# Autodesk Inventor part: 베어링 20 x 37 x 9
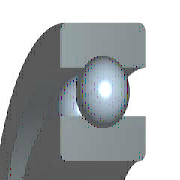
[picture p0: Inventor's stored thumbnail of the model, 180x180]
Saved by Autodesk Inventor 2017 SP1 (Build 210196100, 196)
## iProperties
IsCustomPart: 1
Created: 2012-02
Part Number: 베어링 20 x 37 x 9
Material: 강철, 연강
Description: 깊은 그루브 볼 베어링
Document SubType Name: Modeling
Standard: KS B 2023
Designer: mduedu
Standards Organization: KS
Language: ko-KR
Size Designation: 6904 - 20 x 37 x 9
Categories: <MemberInstance><Categories><Category DisplayName="샤프트 부품" InternalName="7f7aeb1f-a693-4053-b835-cee3144e0d98" Mnemonic="SHFT"><Category DisplayName="베어링" Inter
Density: 7.86 g/cm^3
Mass: 36.2614 g
Surface Area: 48.5817 cm^2
Volume: 4.61341 cm^3
Appearance: 노란색
Author: mduedu
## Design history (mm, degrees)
sketch "스케치" dims "d0" = 4.42 (= -0.26 x WD + 0.26 x BD)
  geometry: L1 (2.29, 14.25)-(6.71, 14.25); L2 (4.5, 14.25)-(4.5, 12.04); L3 (4.5, 14.25)-(4.5, 16.46); L4 (2.858, 12.771)-(0, 12.771); L5 (0, 10)-(9, 10); L6 (2.858, 15.729)-(0, 15.729); L7 (0, 18.5)-(9, 18.5); L8 (9, 10)-(9, 12.771); L9 (6.142, 12.771)-(9, 12.771); L10 (6.142, 15.729)-(9, 15.729); L11 (9, 18.5)-(9, 15.729); L12 (-1.4, 0)-(8.4, 0) reference; L13 (0, -0.3)-(0, 5.3) reference
  constraints: 22 end point, 4 point on line, 2 collinear, 2 perpendicular, 2 symmetric about line, 1 midpoint, 1 parallel, 14 other
  dimensions: "d9" = 20 diameter of L5 L12 (= WD); "d11" = 37 diameter of L7 L12 (= BD); "d12" = 9 distance between parallel lines of L8 L13 (= KB); "d13" = 25.542 diameter of L9 L12 (= 0.326 x BD + 0.674 x WD)
revolve "본체" stored, may be unused: angle "d6" = 90 deg
revolve "볼" stored, may be unused: angle "d7" = 90 deg
pattern_circular "IDS_ARRAYBALL[SIMPL:T]" dims angle "d3" = 360 deg
body "Solid1"
fillet "모깎기1" dims "d1" = 0.3 (= KRS)
other parameters: "WD" = 20 [user parameter; used in 5 equation terms], "BD" = 37 [user parameter; used in 5 equation terms], "KB" = 9 [user parameter; used in 1 equation term], "KRS" = 0.3 [user parameter; used in 1 equation term], "d4" = 0, "d5" = 0, "d8" = 0, "d14" = 0, "d15" = 0, "BBA" = 0 [user parameter], "BC0" = 3304000 [user parameter], "BC" = 6184000 [user parameter], "BR" = 18.5 (= 0.5 x BD) [user parameter]
